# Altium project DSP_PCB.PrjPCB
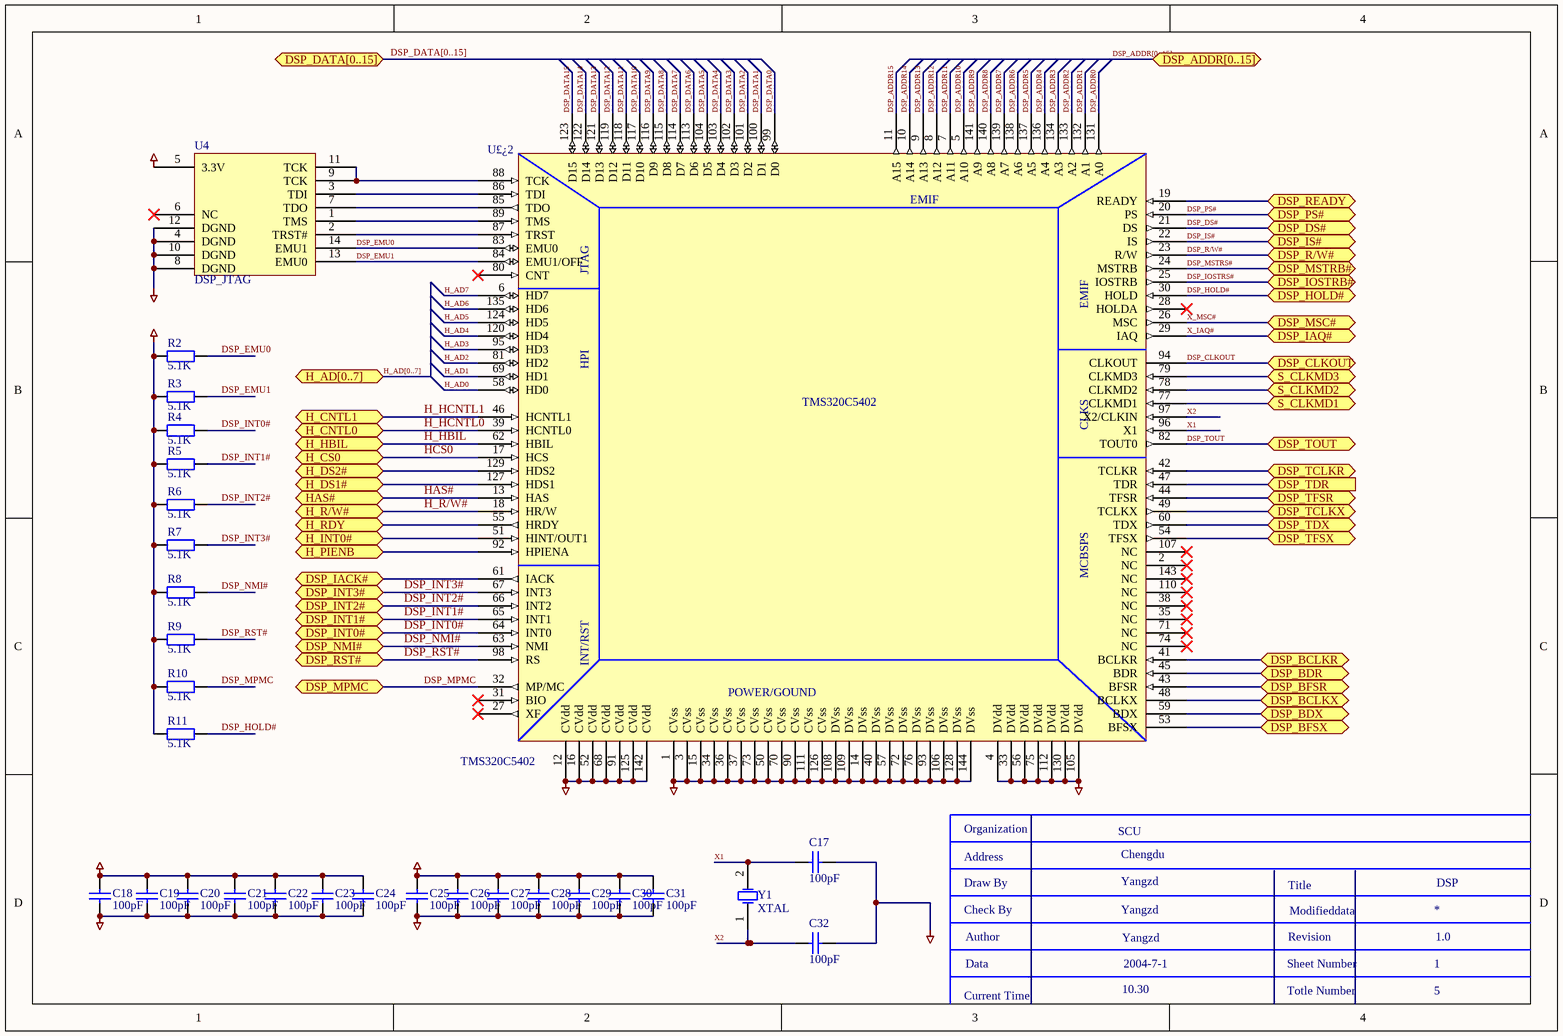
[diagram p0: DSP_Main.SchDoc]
7 sheets, 120 parts. Net scope: flat (ports and power ports of the same name join across sheets).
Sheets:
  DSP_Main.SchDoc
  CPLD.SchDoc
  Memory.SchDoc
  Interface.SchDoc
  Interface2.SchDoc
  Buffer.SchDoc
  Power.SchDoc

## Sheet DSP_Main.SchDoc: DSP
size A4; Date: 2004-7-1; CheckedBy: Yangzd; Author: Yangzd; DrawnBy: Yangzd; Organization: SCU; Address1: Chengdu; DocumentNumber: 1; Revision: 1.0; SheetNumber: 1; SheetTotal: 5

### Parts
C17  100pF  [CC2012-0805]
C18  100pF  [CC2012-0805]
C19  100pF  [CC2012-0805]
C20  100pF  [CC2012-0805]
C21  100pF  [CC2012-0805]
C22  100pF  [CC2012-0805]
C23  100pF  [CC2012-0805]
C24  100pF  [CC2012-0805]
C25  100pF  [CC2012-0805]
C26  100pF  [CC2012-0805]
C27  100pF  [CC2012-0805]
C28  100pF  [CC2012-0805]
C29  100pF  [CC2012-0805]
C30  100pF  [CC2012-0805]
C31  100pF  [CC2012-0805]
C32  100pF  [CC2012-0805]
R2  5.1K  [R2012-0805]
R3  5.1K  [R2012-0805]
R4  5.1K  [R2012-0805]
R5  5.1K  [R2012-0805]
R6  5.1K  [R2012-0805]
R7  5.1K  [R2012-0805]
R8  5.1K  [R2012-0805]
R9  5.1K  [R2012-0805]
R10  5.1K  [R2012-0805]
R11  5.1K  [R2012-0805]
U4  (no value)  [IDC14]
U£¿2  TMS320C5402  [QFP144]
Y1  XTAL  [BCY-W2/D3.1]

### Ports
DSP_ADDR[0..15], DSP_BCLKR, DSP_BCLKX, DSP_BDR, DSP_BDX, DSP_BFSR, DSP_BFSX, DSP_CLKOUT, DSP_DATA[0..15] (bidir), DSP_DS#, DSP_HOLD#, DSP_IACK#, DSP_IAQ#, DSP_INT0#, DSP_INT1#, DSP_INT2#, DSP_INT3#, DSP_IOSTRB#, DSP_IS#, DSP_MPMC, DSP_MSC#, DSP_MSTRB#, DSP_NMI#, DSP_PS#, DSP_R/W#, DSP_READY, DSP_RST#, DSP_TCLKR, DSP_TCLKX, DSP_TDR (in), DSP_TDX, DSP_TFSR, DSP_TFSX, DSP_TOUT, H_AD[0..7] (bidir), H_CNTL0, H_CNTL1, H_CS0, H_DS1#, H_DS2#, H_HBIL, H_INT0#, H_PIENB, H_R/W#, H_RDY, HAS#, S_CLKMD1, S_CLKMD2, S_CLKMD3

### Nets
1.8V: C25.2 C26.2 C27.2 C28.2 C29.2 C30.2 C31.2 U£¿2.12(CVdd) U£¿2.16(CVdd) U£¿2.52(CVdd) U£¿2.68(CVdd) U£¿2.91(CVdd) U£¿2.125(CVdd) U£¿2.142(CVdd)
3.3V: C18.2 C19.2 C20.2 C21.2 C22.2 C23.2 C24.2 R2.1 R3.1 R4.1 R5.1 R6.1 R7.1 R8.1 R9.1 R10.1 R11.1 U4.5(3.3V) U£¿2.4(DVdd) U£¿2.33(DVdd) U£¿2.56(DVdd) U£¿2.75(DVdd) U£¿2.105(DVdd) U£¿2.112(DVdd) U£¿2.130(DVdd)
DGND: C17.1 C18.1 C19.1 C20.1 C21.1 C22.1 C23.1 C24.1 C25.1 C26.1 C27.1 C28.1 C29.1 C30.1 C31.1 C32.1 U4.4(DGND) U4.8(DGND) U4.10(DGND) U4.12(DGND) U£¿2.1(CVss) U£¿2.3(CVss) U£¿2.14(DVss) U£¿2.15(CVss) U£¿2.34(CVss) U£¿2.36(CVss) U£¿2.37(CVss) U£¿2.40(DVss) U£¿2.50(CVss) U£¿2.57(DVss) U£¿2.70(CVss) U£¿2.72(DVss) U£¿2.73(CVss) U£¿2.76(DVss) U£¿2.90(CVss) U£¿2.93(DVss) U£¿2.106(DVss) U£¿2.108(DVss) U£¿2.109(DVss) U£¿2.111(CVss) U£¿2.126(CVss) U£¿2.128(DVss) U£¿2.144(DVss)
DSP_ADDR0: U£¿2.131(A0)
DSP_ADDR1: U£¿2.132(A1)
DSP_ADDR2: U£¿2.133(A2)
DSP_ADDR3: U£¿2.134(A3)
DSP_ADDR4: U£¿2.136(A4)
DSP_ADDR5: U£¿2.137(A5)
DSP_ADDR6: U£¿2.138(A6)
DSP_ADDR7: U£¿2.139(A7)
DSP_ADDR8: U£¿2.140(A8)
DSP_ADDR9: U£¿2.141(A9)
DSP_ADDR10: U£¿2.5(A10)
DSP_ADDR11: U£¿2.7(A11)
DSP_ADDR12: U£¿2.8(A12)
DSP_ADDR13: U£¿2.9(A13)
DSP_ADDR14: U£¿2.10(A14)
DSP_ADDR15: U£¿2.11(A15)
DSP_CLKOUT: U£¿2.94(CLKOUT) ; port DSP_CLKOUT
DSP_DATA0: U£¿2.99(D0)
DSP_DATA1: U£¿2.100(D1)
DSP_DATA2: U£¿2.101(D2)
DSP_DATA3: U£¿2.102(D3)
DSP_DATA4: U£¿2.103(D4)
DSP_DATA5: U£¿2.104(D5)
DSP_DATA6: U£¿2.113(D6)
DSP_DATA7: U£¿2.114(D7)
DSP_DATA8: U£¿2.115(D8)
DSP_DATA9: U£¿2.116(D9)
DSP_DATA10: U£¿2.117(D10)
DSP_DATA11: U£¿2.118(D11)
DSP_DATA12: U£¿2.119(D12)
DSP_DATA13: U£¿2.121(D13)
DSP_DATA14: U£¿2.122(D14)
DSP_DATA15: U£¿2.123(D15)
DSP_DS#: U£¿2.21(DS) ; port DSP_DS#
DSP_EMU0: R2.2 U4.14(EMU1) U£¿2.83(EMU0)
DSP_EMU1: R3.2 U4.13(EMU0) U£¿2.84(EMU1/OFF)
DSP_HOLD#: R11.2 U£¿2.30(HOLD) ; port DSP_HOLD#
DSP_INT0#: R4.2 U£¿2.64(INT0) ; port DSP_INT0#
DSP_INT1#: R5.2 U£¿2.65(INT1) ; port DSP_INT1#
DSP_INT2#: R6.2 U£¿2.66(INT2) ; port DSP_INT2#
DSP_INT3#: R7.2 U£¿2.67(INT3) ; port DSP_INT3#
DSP_IOSTRS#: U£¿2.25(IOSTRB) ; port DSP_IOSTRB#
DSP_IS#: U£¿2.22(IS) ; port DSP_IS#
DSP_MPMC: R10.2 U£¿2.32(MP/MC) ; port DSP_MPMC
DSP_MSTRS#: U£¿2.24(MSTRB) ; port DSP_MSTRB#
DSP_NMI#: R8.2 U£¿2.63(NMI) ; port DSP_NMI#
DSP_PS#: U£¿2.20(PS) ; port DSP_PS#
DSP_R/W#: U£¿2.23(R/W) ; port DSP_R/W#
DSP_RST#: R9.2 U£¿2.98(RS) ; port DSP_RST#
DSP_TOUT: U£¿2.82(TOUT0) ; port DSP_TOUT
H_AD0: U£¿2.58(HD0)
H_AD1: U£¿2.69(HD1)
H_AD2: U£¿2.81(HD2)
H_AD3: U£¿2.95(HD3)
H_AD4: U£¿2.120(HD4)
H_AD5: U£¿2.124(HD5)
H_AD6: U£¿2.135(HD6)
H_AD7: U£¿2.6(HD7)
H_HBIL: U£¿2.62(HBIL) ; port H_HBIL
H_HCNTL0: U£¿2.39(HCNTL0) ; port H_CNTL0
H_HCNTL1: U£¿2.46(HCNTL1) ; port H_CNTL1
H_R/W#: U£¿2.18(HR/W) ; port H_R/W#
HAS#: U£¿2.13(HAS) ; port HAS#
HCS0: U£¿2.17(HCS) ; port H_CS0
X1: C17.2 U£¿2.96(X1) Y1.2(OSC2)
X2: U£¿2.97(X2/CLKIN)
X_IAQ#: U£¿2.29(IAQ) ; port DSP_IAQ#
X_MSC#: U£¿2.26(MSC) ; port DSP_MSC#
NetC32_2: C32.2 Y1.1(OSC1)
NetJP3_8: U£¿2.127(HDS1) ; port H_DS1#
NetJP3_9: U£¿2.129(HDS2) ; port H_DS2#
NetR15_1: U£¿2.79(CLKMD3) ; port S_CLKMD3
NetR16_1: U£¿2.78(CLKMD2) ; port S_CLKMD2
NetR17_1: U£¿2.77(CLKMD1) ; port S_CLKMD1
NetU3_76: U£¿2.19(READY) ; port DSP_READY
NetU4_1: U4.1(TMS) U£¿2.89(TMS)
NetU4_2: U4.2(TRST#) U£¿2.87(TRST)
NetU4_3: U4.3(TDI) U£¿2.86(TDI)
NetU4_7: U4.7(TDO) U£¿2.85(TDO)
NetU4_9: U4.9(TCK) U4.11(TCK) U£¿2.88(TCK)
NetU5_16: U£¿2.47(TDR) ; port DSP_TDR
NetU5_17: U£¿2.45(BDR) ; port DSP_BDR
NetU5_19: U£¿2.44(TFSR) ; port DSP_TFSR
NetU5_20: U£¿2.43(BFSR) ; port DSP_BFSR
NetU5_22: U£¿2.42(TCLKR) ; port DSP_TCLKR
NetU5_23: U£¿2.41(BCLKR) ; port DSP_BCLKR
NetU5_35: U£¿2.48(BCLKX) ; port DSP_BCLKX
NetU5_36: U£¿2.49(TCLKX) ; port DSP_TCLKX
NetU5_37: U£¿2.51(HINT/OUT1) ; port H_INT0#
NetU5_38: U£¿2.53(BFSX) ; port DSP_BFSX
NetU5_40: U£¿2.54(TFSX) ; port DSP_TFSX
NetU5_41: U£¿2.55(HRDY) ; port H_RDY
NetU5_43: U£¿2.59(BDX) ; port DSP_BDX
NetU£¿2_60: U£¿2.60(TDX) ; port DSP_TDX
NetU£¿2_61: U£¿2.61(IACK) ; port DSP_IACK#
NetU£¿2_92: U£¿2.92(HPIENA) ; port H_PIENB

Not connected (* = marked no-connect by the designer): U4 6(NC)*; U£¿2 2(NC)* 27(XF)* 28(HOLDA)* 31(BIO)* 35(NC)* 38(NC)* 71(NC)* 74(NC)* 80(CNT)* 107(NC)* 110(NC)* 143(NC)*

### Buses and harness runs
bus DSP_ADDR[0..15] = port DSP_ADDR[0..15]
bus DSP_DATA[0..15] = port DSP_DATA[0..15]
bus H_AD[0..7] = port H_AD[0..7]

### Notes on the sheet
- Organization
- Draw By
- Check By
- Address
- Title
- Modifieddata
- Data
- Author
- Sheet Number
- Revision
- Current Time
- Totle Number
- Labels drawn without touching a wire or pin: X2

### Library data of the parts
C17-C32 = Cap: Capacitor; Manufacturer: Generic Components; Class I: Passive
R2-R11 = Res2: Resistor; Manufacturer: Generic Components; Class I: Passive
U4 = DSP_JTAG
U£¿2 = TMS320C5402: FIXED-POINT DIGITAL SIGNAL PROCESSORS
Y1 = XTAL: Crystal Oscillator; Manufacturer: Generic Components

## Sheet CPLD.SchDoc
size A4
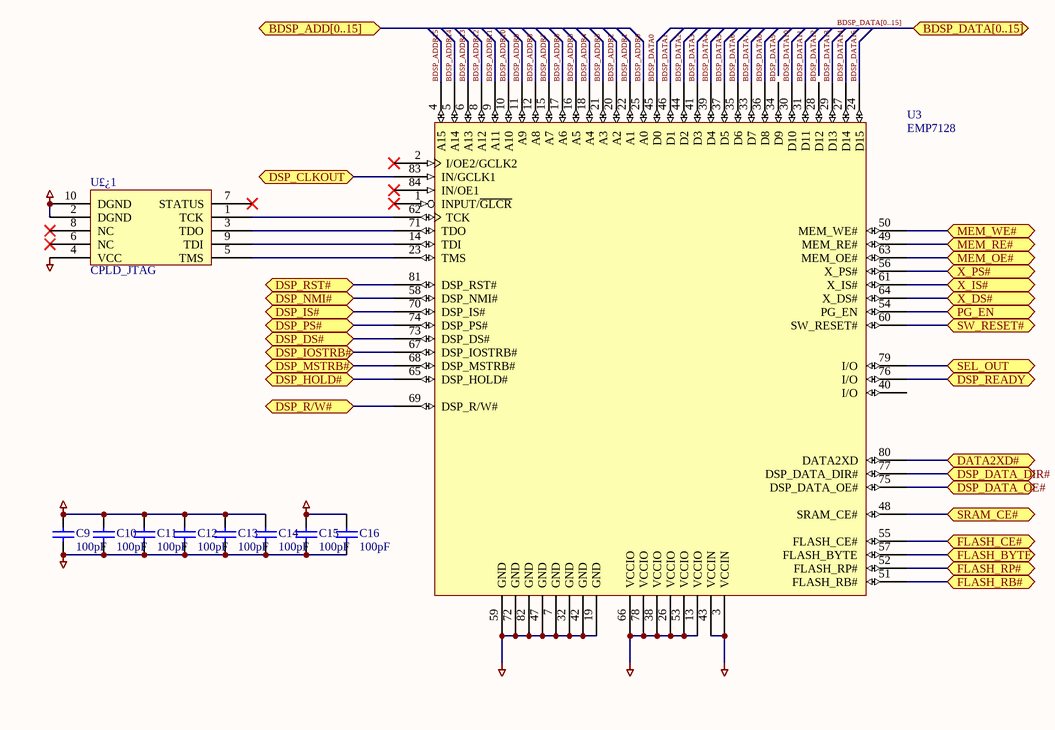
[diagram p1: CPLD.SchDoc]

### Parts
(Parts that share a designator on the sheet are numbered #1, #2 ... from top to bottom, then left to right.)
C9#1  100pF  [CC2012-0805]
C10#1  100pF  [CC2012-0805]
C11#1  100pF  [CC2012-0805]
C12#1  100pF  [CC2012-0805]
C13  100pF  [CC2012-0805]
C14  100pF  [CC2012-0805]
C15  100pF  [CC2012-0805]
C16  100pF  [CC2012-0805]
U3  EMP7128  [HPLCC84]
U£¿1  CPLD_JTAG  [IDC10]

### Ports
BDSP_ADD[0..15], BDSP_DATA[0..15], DATA2XD#, DSP_CLKOUT, DSP_DATA_DIR#, DSP_DATA_OE#, DSP_DS#, DSP_HOLD#, DSP_IOSTRB#, DSP_IS#, DSP_MSTRB#, DSP_NMI#, DSP_PS#, DSP_R/W#, DSP_READY, DSP_RST#, FLASH_BYTE, FLASH_CE#, FLASH_RB#, FLASH_RP#, MEM_OE#, MEM_RE#, MEM_WE#, PG_EN, SEL_OUT, SRAM_CE#, SW_RESET#, X_DS#, X_IS#, X_PS#

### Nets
3.3V: C9#1.1 C10#1.2 C11#1.2 C12#1.2 C13.2 C14.2 U3.13(VCCIO) U3.26(VCCIO) U3.38(VCCIO) U3.53(VCCIO) U3.66(VCCIO) U3.78(VCCIO) U£¿1.4(VCC)
5V: C15.2 C16.2 U3.3(VCCIN) U3.43(VCCIN)
DGND: C9#1.2 C10#1.1 C11#1.1 C12#1.1 C13.1 C14.1 C15.1 C16.1 U3.7(GND) U3.19(GND) U3.32(GND) U3.42(GND) U3.47(GND) U3.59(GND) U3.72(GND) U3.82(GND) U£¿1.2(DGND) U£¿1.10(DGND)
BDSP_ADDR0: U3.25(A0)
BDSP_ADDR1: U3.22(A1)
BDSP_ADDR2: U3.20(A2)
BDSP_ADDR3: U3.21(A3)
BDSP_ADDR4: U3.18(A4)
BDSP_ADDR5: U3.16(A5)
BDSP_ADDR6: U3.17(A6)
BDSP_ADDR7: U3.15(A7)
BDSP_ADDR8: U3.12(A8)
BDSP_ADDR9: U3.11(A9)
BDSP_ADDR10: U3.10(A10)
BDSP_ADDR11: U3.9(A11)
BDSP_ADDR12: U3.8(A12)
BDSP_ADDR13: U3.6(A13)
BDSP_ADDR14: U3.5(A14)
BDSP_ADDR15: U3.4(A15)
BDSP_DATA0: U3.45(D0)
BDSP_DATA1: U3.46(D1)
BDSP_DATA2: U3.44(D2)
BDSP_DATA3: U3.41(D3)
BDSP_DATA4: U3.39(D4)
BDSP_DATA5: U3.37(D5)
BDSP_DATA6: U3.35(D6)
BDSP_DATA7: U3.33(D7)
BDSP_DATA8: U3.36(D8)
BDSP_DATA9: U3.34(D9)
BDSP_DATA10: U3.30(D10)
BDSP_DATA11: U3.31(D11)
BDSP_DATA12: U3.28(D12)
BDSP_DATA13: U3.29(D13)
BDSP_DATA14: U3.27(D14)
BDSP_DATA15: U3.24(D15)
DSP_CLKOUT: U3.83(IN/GCLK1) ; port DSP_CLKOUT
DSP_DATA_DIR: U3.77(DSP_DATA_DIR#) ; port DSP_DATA_DIR#
DSP_DATA_OE#: U3.75(DSP_DATA_OE#) ; port DSP_DATA_OE#
DSP_DS#: U3.73(DSP_DS#) ; port DSP_DS#
DSP_HOLD#: U3.65(DSP_HOLD#) ; port DSP_HOLD#
DSP_IOSTRS#: U3.67(DSP_IOSTRB#) ; port DSP_IOSTRB#
DSP_IS#: U3.70(DSP_IS#) ; port DSP_IS#
DSP_MSTRS#: U3.68(DSP_MSTRB#) ; port DSP_MSTRB#
DSP_NMI#: U3.58(DSP_NMI#) ; port DSP_NMI#
DSP_PS#: U3.74(DSP_PS#) ; port DSP_PS#
DSP_R/W#: U3.69(DSP_R/W#) ; port DSP_R/W#
DSP_RST#: U3.81(DSP_RST#) ; port DSP_RST#
FLASH_BYTE: U3.57(FLASH_BYTE) ; port FLASH_BYTE
FLASH_CE#: U3.55(FLASH_CE#) ; port FLASH_CE#
FLASH_RB: U3.51(FLASH_RB#) ; port FLASH_RB#
FLASH_RP: U3.52(FLASH_RP#) ; port FLASH_RP#
MEM_R#: U3.49(MEM_RE#) ; port MEM_RE#
MEM_WE#: U3.50(MEM_WE#) ; port MEM_WE#
SRAM_CE#: U3.48(SRAM_CE#) ; port SRAM_CE#
NetR14_1: U3.60(SW_RESET#) ; port SW_RESET#
NetU3_14: U3.14(TDI) U£¿1.9(TDI)
NetU3_23: U3.23(TMS) U£¿1.5(TMS)
NetU3_54: U3.54(PG_EN) ; port PG_EN
NetU3_56: U3.56(X_PS#) ; port X_PS#
NetU3_61: U3.61(X_IS#) ; port X_IS#
NetU3_62: U3.62(TCK) U£¿1.1(TCK)
NetU3_63: U3.63(MEM_OE#) ; port MEM_OE#
NetU3_64: U3.64(X_DS#) ; port X_DS#
NetU3_71: U3.71(TDO) U£¿1.3(TDO)
NetU3_76: U3.76(I/O) ; port DSP_READY
NetU3_79: U3.79(I/O) ; port SEL_OUT
NetU3_80: U3.80(DATA2XD) ; port DATA2XD#

Not connected (* = marked no-connect by the designer): U3 1(INPUT/~{GLCR})* 2(I/OE2/GCLK2)* 40(I/O) 84(IN/OE1)*; U£¿1 6(NC)* 7(STATUS)* 8(NC)*

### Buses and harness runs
bus BDSP_DATA[0..15] = port BDSP_DATA[0..15]

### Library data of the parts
C9#1 C10#1 C11#1 C12#1 C13-C16 = Cap: as C17 on sheet DSP_Main
U3 = EMP7128: CPLD

## Sheet Memory.SchDoc
size A4
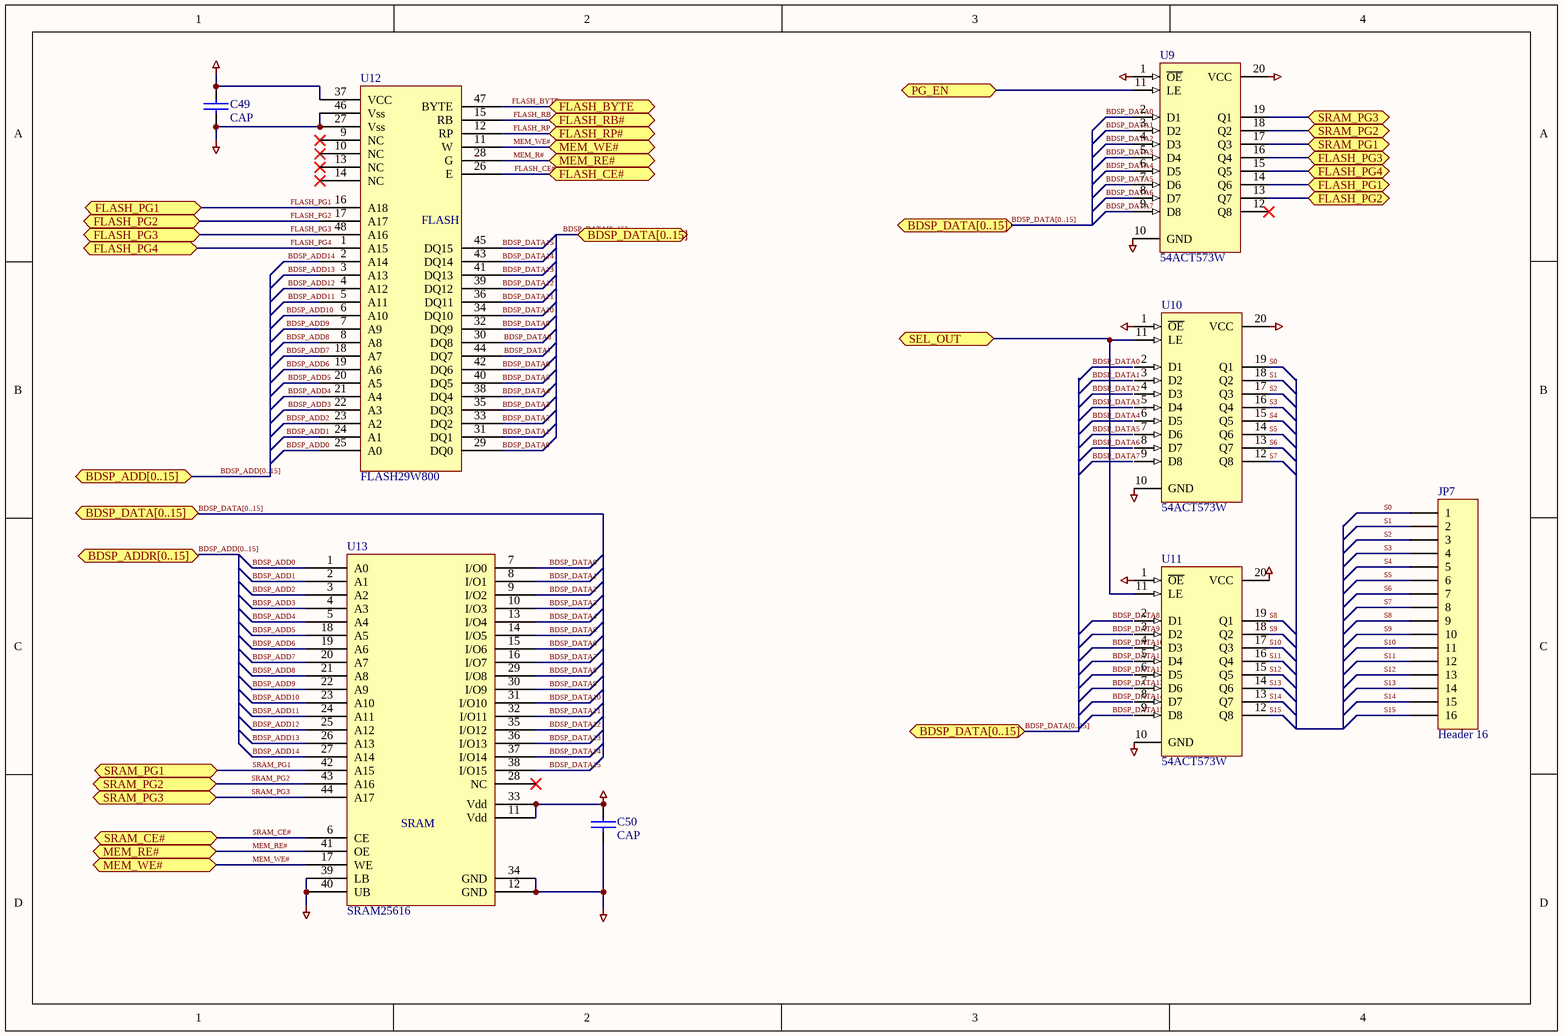
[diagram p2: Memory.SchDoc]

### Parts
C49  CAP  [CC2012-0805]
C50  CAP  [CC2012-0805]
JP7  Header 16  [HDR1X16]
U9  54ACT573W  [CDFP-G20/C10]
U10  54ACT573W  [CDFP-G20/C10]
U11  54ACT573W  [CDFP-G20/C10]
U12  FLASH29W800  [TSSO12X20-G48/P.5]
U13  SRAM25616  [TSOP44]

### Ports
BDSP_ADD[0..15], BDSP_ADDR[0..15], BDSP_DATA[0..15], FLASH_BYTE, FLASH_CE#, FLASH_PG1, FLASH_PG2, FLASH_PG3, FLASH_PG4, FLASH_RB#, FLASH_RP#, MEM_RE#, MEM_WE#, PG_EN, SEL_OUT, SRAM_CE#, SRAM_PG1, SRAM_PG2, SRAM_PG3

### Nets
3.3V: C49.1 C50.1 U12.37(VCC) U13.11(Vdd) U13.33(Vdd)
5V: U9.20(VCC) U10.20(VCC) U11.20(VCC)
DGND: C49.2 C50.2 U9.1(~{OE}) U9.10(GND) U10.1(~{OE}) U10.10(GND) U11.1(~{OE}) U11.10(GND) U12.27(Vss) U12.46(Vss) U13.12(GND) U13.34(GND) U13.39(LB) U13.40(UB)
BDSP_ADD0: U12.25(A0) U13.1(A0)
BDSP_ADD1: U12.24(A1) U13.2(A1)
BDSP_ADD2: U12.23(A2) U13.3(A2)
BDSP_ADD3: U12.22(A3) U13.4(A3)
BDSP_ADD4: U12.21(A4) U13.5(A4)
BDSP_ADD5: U12.20(A5) U13.18(A5)
BDSP_ADD6: U12.19(A6) U13.19(A6)
BDSP_ADD7: U12.18(A7) U13.20(A7)
BDSP_ADD8: U12.8(A8) U13.21(A8)
BDSP_ADD9: U12.7(A9) U13.22(A9)
BDSP_ADD10: U12.6(A10) U13.23(A10)
BDSP_ADD11: U12.5(A11) U13.24(A11)
BDSP_ADD12: U12.4(A12) U13.25(A12)
BDSP_ADD13: U12.3(A13) U13.26(A13)
BDSP_ADD14: U12.2(A14) U13.27(A14)
BDSP_DATA0: U9.2(D1) U12.29(DQ0) U13.7(I/O0)
BDSP_DATA1: U9.3(D2) U12.31(DQ1) U13.8(I/O1)
BDSP_DATA2: U9.4(D3) U12.33(DQ2) U13.9(I/O2)
BDSP_DATA3: U9.5(D4) U12.35(DQ3) U13.10(I/O3)
BDSP_DATA4: U9.6(D5) U12.38(DQ4) U13.13(I/O4)
BDSP_DATA5: U9.7(D6) U12.40(DQ5) U13.14(I/O5)
BDSP_DATA6: U9.8(D7) U12.42(DQ6) U13.15(I/O6)
BDSP_DATA7: U9.9(D8) U12.44(DQ7) U13.16(I/O7)
BDSP_DATA8: U12.30(DQ8) U13.29(I/O8)
BDSP_DATA9: U12.32(DQ9) U13.30(I/O9)
BDSP_DATA10: U12.34(DQ10) U13.31(I/O10)
BDSP_DATA11: U12.36(DQ11) U13.32(I/O11)
BDSP_DATA12: U12.39(DQ12) U13.35(I/O12)
BDSP_DATA13: U12.41(DQ13) U13.36(I/O13)
BDSP_DATA14: U12.43(DQ14) U13.37(I/O14)
BDSP_DATA15: U12.45(DQ15) U13.38(I/O15)
FLASH_BYTE: U12.47(BYTE) ; port FLASH_BYTE
FLASH_CE#: U12.26(E) ; port FLASH_CE#
FLASH_PG1: U9.14(Q6) U12.16(A18) ; port FLASH_PG1
FLASH_PG2: U9.13(Q7) U12.17(A17) ; port FLASH_PG2
FLASH_PG3: U9.16(Q4) U12.48(A16) ; port FLASH_PG3
FLASH_PG4: U9.15(Q5) U12.1(A15) ; port FLASH_PG4
FLASH_RB: U12.15(RB) ; port FLASH_RB#
FLASH_RP: U12.12(RP) ; port FLASH_RP#
MEM_R#: U12.28(G) U13.41(OE) ; port MEM_RE#  [also labelled MEM_RE#]
MEM_WE#: U12.11(W) U13.17(WE) ; port MEM_WE#
S0: JP7.1 U10.19(Q1)
S1: JP7.2 U10.18(Q2)
S2: JP7.3 U10.17(Q3)
S3: JP7.4 U10.16(Q4)
S4: JP7.5 U10.15(Q5)
S5: JP7.6 U10.14(Q6)
S6: JP7.7 U10.13(Q7)
S7: JP7.8 U10.12(Q8)
S8: JP7.9 U11.19(Q1)
S9: JP7.10 U11.18(Q2)
S10: JP7.11 U11.17(Q3)
S11: JP7.12 U11.16(Q4)
S12: JP7.13 U11.15(Q5)
S13: JP7.14 U11.14(Q6)
S14: JP7.15 U11.13(Q7)
S15: JP7.16 U11.12(Q8)
SRAM_CE#: U13.6(CE) ; port SRAM_CE#
SRAM_PG1: U9.17(Q3) U13.42(A15) ; port SRAM_PG1
SRAM_PG2: U9.18(Q2) U13.43(A16) ; port SRAM_PG2
SRAM_PG3: U9.19(Q1) U13.44(A17) ; port SRAM_PG3
NetU3_54: U9.11(LE) ; port PG_EN
NetU3_79: U10.11(LE) U11.11(LE) ; port SEL_OUT

Not connected (* = marked no-connect by the designer): U9 12(Q8); U10 2(D1) 3(D2) 4(D3) 5(D4) 6(D5) 7(D6) 8(D7) 9(D8); U11 2(D1) 3(D2) 4(D3) 5(D4) 6(D5) 7(D6) 8(D7) 9(D8); U12 9(NC)* 10(NC)* 13(NC)* 14(NC)*; U13 28(NC)*

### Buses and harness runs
bus BDSP_ADD[0..15]
bus BDSP_ADD[0..15] = port BDSP_ADD[0..15]
bus BDSP_DATA[0..15]
bus BDSP_DATA[0..15] = port BDSP_DATA[0..15]

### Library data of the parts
C49 C50 = CAP: Capacitor
JP7 = Header 16: Header, 16-Pin; Manufacturer: Generic Components; Class I: Connector
U9-U11 = 54ACT573W: Octal D-Type Transparent Latch with 3-State Outputs; Manufacturer: Texas Instruments; Package Information: Latest Revision: Jan-1995; Class I: Logic
U12 = FLASH29W800: FLASH RAM
U13 = SRAM25616: SRAM

## Sheet Interface.SchDoc
size A4
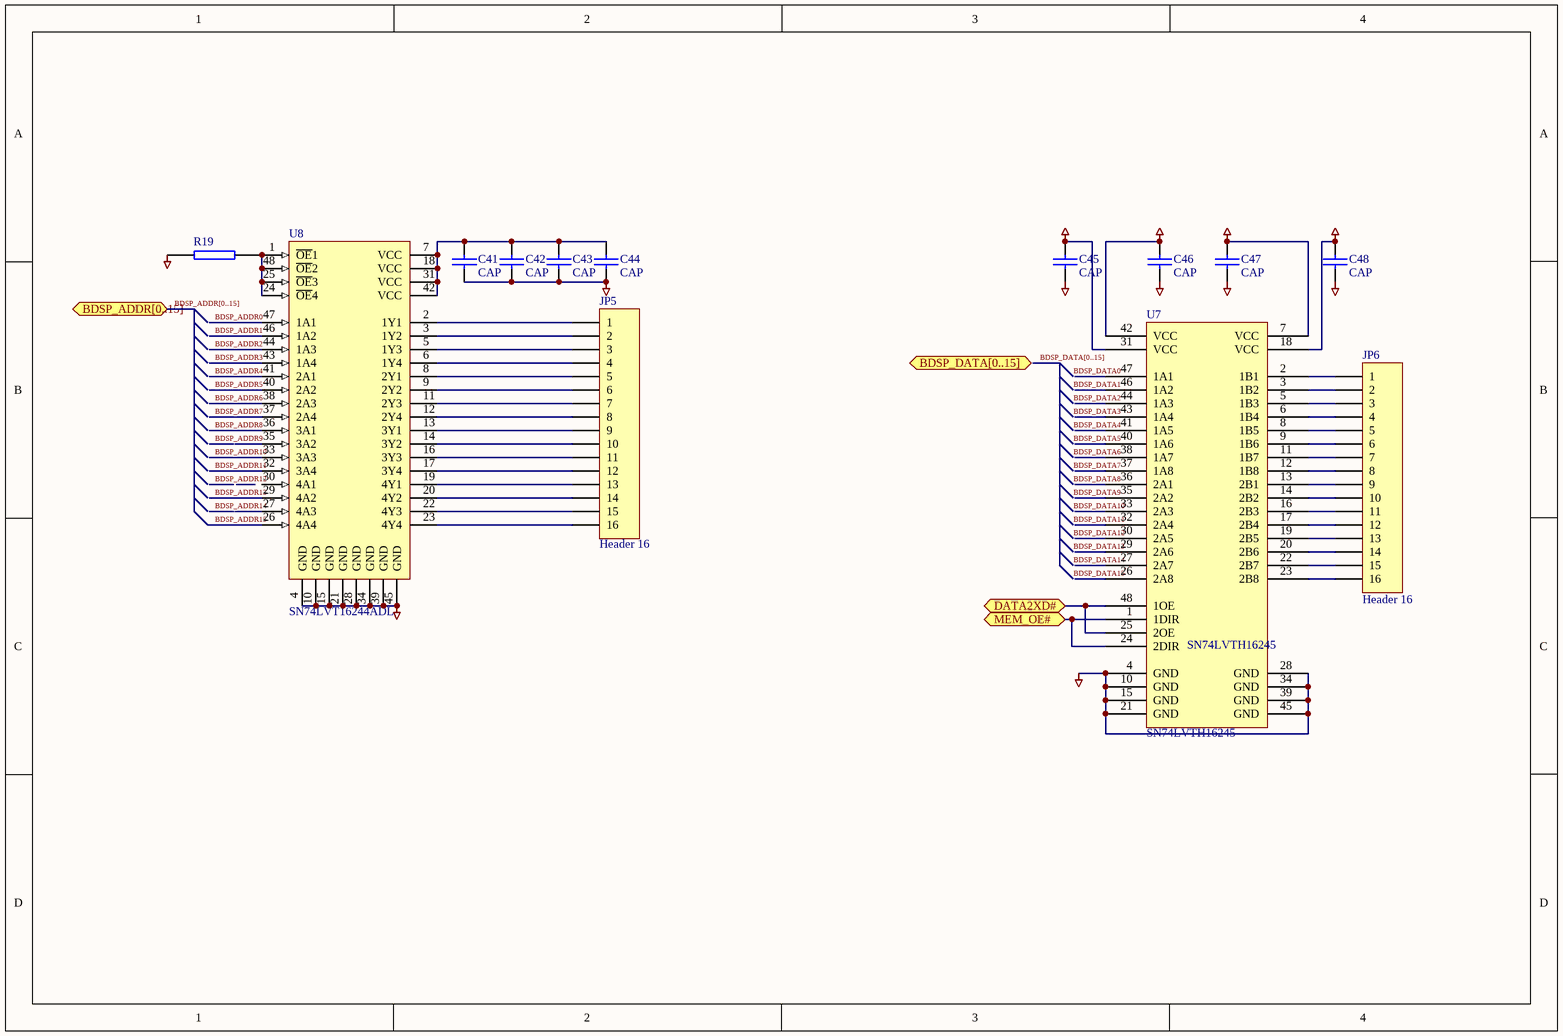
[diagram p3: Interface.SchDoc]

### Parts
C41  CAP  [CC2012-0805]
C42  CAP  [CC2012-0805]
C43  CAP  [CC2012-0805]
C44  CAP  [CC2012-0805]
C45  CAP  [CC2012-0805]
C46  CAP  [CC2012-0805]
C47  CAP  [CC2012-0805]
C48  CAP  [CC2012-0805]
JP5  Header 16  [HDR1X16]
JP6  Header 16  [HDR1X16]
R19  (no value)  [R2012-0805]
U7  SN74LVTH16245  [TSOP48]
U8  SN74LVT16244ADL  [SSO-G48]

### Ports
BDSP_ADDR[0..15], BDSP_DATA[0..15], DATA2XD#, MEM_OE#

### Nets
3.3V: C45.1 C46.1 C47.1 C48.1 U7.7(VCC) U7.18(VCC) U7.31(VCC) U7.42(VCC)
DGND: C41.2 C42.2 C43.2 C44.2 C45.2 C46.2 C47.2 C48.2 R19.2 U7.4(GND) U7.10(GND) U7.15(GND) U7.21(GND) U7.28(GND) U7.34(GND) U7.39(GND) U7.45(GND) U8.4(GND) U8.10(GND) U8.15(GND) U8.21(GND) U8.28(GND) U8.34(GND) U8.39(GND) U8.45(GND)
BDSP_ADDR0: U8.47(1A1)
BDSP_ADDR1: U8.46(1A2)
BDSP_ADDR2: U8.44(1A3)
BDSP_ADDR3: U8.43(1A4)
BDSP_ADDR4: U8.41(2A1)
BDSP_ADDR5: U8.40(2A2)
BDSP_ADDR6: U8.38(2A3)
BDSP_ADDR7: U8.37(2A4)
BDSP_ADDR8: U8.36(3A1)
BDSP_ADDR10: U8.33(3A3)
BDSP_ADDR11: U8.32(3A4)
BDSP_ADDR13: U8.29(4A2)
BDSP_ADDR15: U8.26(4A4)
NetC41_1: C41.1 C42.1 C43.1 C44.1 U8.7(VCC) U8.18(VCC) U8.31(VCC) U8.42(VCC)
NetJP5_1: JP5.1 U8.2(1Y1)
NetJP5_2: JP5.2 U8.3(1Y2)
NetJP5_3: JP5.3 U8.5(1Y3)
NetJP5_4: JP5.4 U8.6(1Y4)
NetJP5_5: JP5.5 U8.8(2Y1)
NetJP5_6: JP5.6 U8.9(2Y2)
NetJP5_7: JP5.7 U8.11(2Y3)
NetJP5_8: JP5.8 U8.12(2Y4)
NetJP5_9: JP5.9 U8.13(3Y1)
NetJP5_10: JP5.10 U8.14(3Y2)
NetJP5_11: JP5.11 U8.16(3Y3)
NetJP5_12: JP5.12 U8.17(3Y4)
NetJP5_13: JP5.13 U8.19(4Y1)
NetJP5_14: JP5.14 U8.20(4Y2)
NetJP5_15: JP5.15 U8.22(4Y3)
NetJP5_16: JP5.16 U8.23(4Y4)
NetJP6_1: JP6.1 U7.2(1B1)
NetJP6_2: JP6.2 U7.3(1B2)
NetJP6_3: JP6.3 U7.5(1B3)
NetJP6_4: JP6.4 U7.6(1B4)
NetJP6_5: JP6.5 U7.8(1B5)
NetJP6_6: JP6.6 U7.9(1B6)
NetJP6_7: JP6.7 U7.11(1B7)
NetJP6_8: JP6.8 U7.12(1B8)
NetJP6_9: JP6.9 U7.13(2B1)
NetJP6_10: JP6.10 U7.14(2B2)
NetJP6_11: JP6.11 U7.16(2B3)
NetJP6_12: JP6.12 U7.17(2B4)
NetJP6_13: JP6.13 U7.19(2B5)
NetJP6_14: JP6.14 U7.20(2B6)
NetJP6_15: JP6.15 U7.22(2B7)
NetJP6_16: JP6.16 U7.23(2B8)
NetR19_1: R19.1 U8.1(~{OE}1) U8.24(~{OE}4) U8.25(~{OE}3) U8.48(~{OE}2)
NetU3_63: U7.1(1DIR) U7.24(2DIR) ; port MEM_OE#
NetU3_80: U7.25(2OE) U7.48(1OE) ; port DATA2XD#

Not connected (* = marked no-connect by the designer): U7 26(2A8) 27(2A7) 29(2A6) 30(2A5) 32(2A4) 33(2A3) 35(2A2) 36(2A1) 37(1A8) 38(1A7) 40(1A6) 41(1A5) 43(1A4) 44(1A3) 46(1A2) 47(1A1); U8 27(4A3) 30(4A1) 35(3A2)

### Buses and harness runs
bus BDSP_ADDR[0..15] = port BDSP_ADDR[0..15]
bus BDSP_DATA[0..15]

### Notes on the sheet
- Labels drawn without touching a wire or pin: BDSP_DATA0, BDSP_DATA1, BDSP_DATA2, BDSP_DATA3, BDSP_DATA4, BDSP_DATA5, BDSP_DATA6, BDSP_DATA7, BDSP_DATA8, BDSP_DATA9, BDSP_DATA10, BDSP_DATA11, BDSP_DATA12, BDSP_DATA13, BDSP_DATA14, BDSP_DATA15

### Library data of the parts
C41-C48 = CAP: Capacitor
JP5 JP6 = Header 16: as JP7 on sheet Memory
R19 = RES2
U8 = SN74LVT16244ADL: 3.3-V ABT 16-Bit Buffer/Driver with 3-State Outputs; Manufacturer: Texas Instruments; Package Information: Latest Revision: Jan-1998; Class I: Logic; Class II: Buffer/Line Driver

## Sheet Interface2.SchDoc
size A4
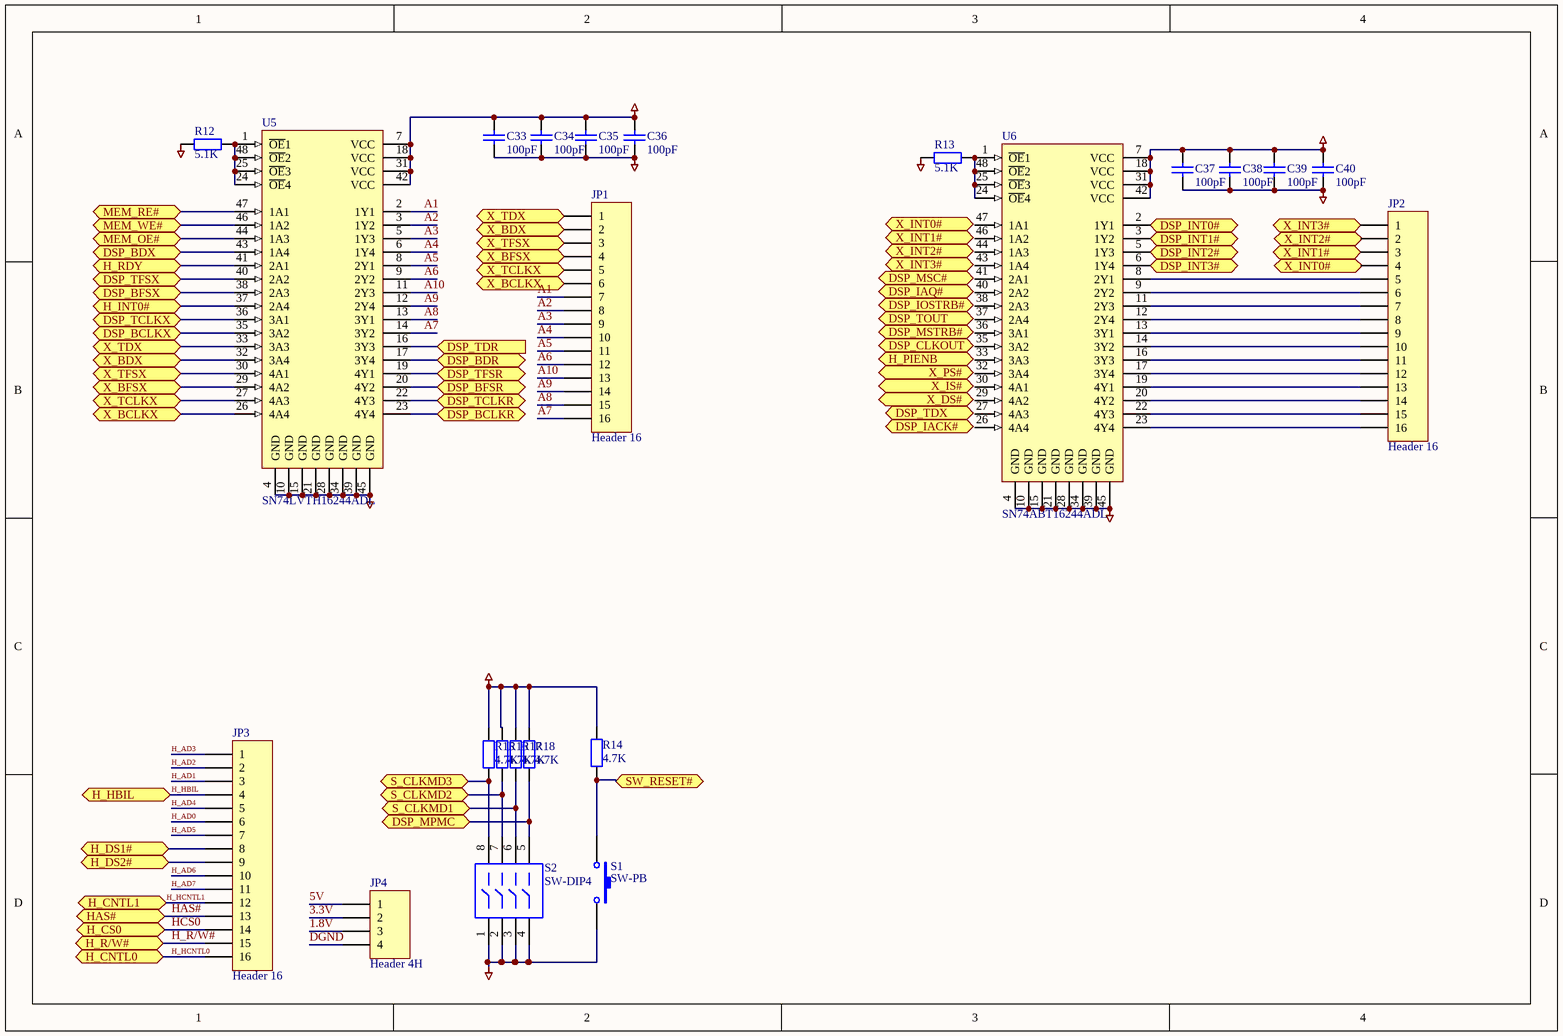
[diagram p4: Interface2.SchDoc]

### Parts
C33  100pF  [CC2012-0805]
C34  100pF  [CC2012-0805]
C35  100pF  [CC2012-0805]
C36  100pF  [CC2012-0805]
C37  100pF  [CC2012-0805]
C38  100pF  [CC2012-0805]
C39  100pF  [CC2012-0805]
C40  100pF  [CC2012-0805]
JP1  Header 16  [HDR1X16]
JP2  Header 16  [HDR1X16]
JP3  Header 16  [HDR1X16]
JP4  Header 4H  [HDR1X4H]
R12  5.1K  [R2012-0805]
R13  5.1K  [R2012-0805]
R14  4.7K  [R2012-0805]
R15  4.7K  [R2012-0805]
R16  4.7K  [R2012-0805]
R17  4.7K  [R2012-0805]
R18  4.7K  [R2012-0805]
S1  SW-PB  [SPST-2]
S2  SW-DIP4  [DIP-8]
U5  SN74LVTH16244ADL  [SSO-G48]
U6  SN74ABT16244ADL  [SSO-G48]

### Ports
DSP_BCLKR, DSP_BCLKX, DSP_BDR, DSP_BDX, DSP_BFSR, DSP_BFSX, DSP_CLKOUT, DSP_IACK#, DSP_IAQ#, DSP_INT0#, DSP_INT1#, DSP_INT2#, DSP_INT3#, DSP_IOSTRB#, DSP_MPMC, DSP_MSC#, DSP_MSTRB#, DSP_TCLKR, DSP_TCLKX, DSP_TDR (in), DSP_TDX, DSP_TFSR, DSP_TFSX, DSP_TOUT, H_CNTL0, H_CNTL1, H_CS0, H_DS1#, H_DS2#, H_HBIL, H_INT0#, H_PIENB, H_R/W#, H_RDY, HAS#, MEM_OE#, MEM_RE#, MEM_WE#, S_CLKMD1, S_CLKMD2, S_CLKMD3, SW_RESET#, X_BCLKX, X_BDX, X_BFSX, X_DS#, X_INT0#, X_INT1#, X_INT2#, X_INT3#, X_IS#, X_PS#, X_TCLKX, X_TDX, X_TFSX

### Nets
3.3V: C33.2 C34.2 C35.2 C36.2 C37.2 C38.2 C39.2 C40.2 JP4.2 R14.2 R15.2 R16.2 R17.2 R18.2 U5.7(VCC) U5.18(VCC) U5.31(VCC) U5.42(VCC) U6.7(VCC) U6.18(VCC) U6.31(VCC) U6.42(VCC)
DGND: C33.1 C34.1 C35.1 C36.1 C37.1 C38.1 C39.1 C40.1 JP4.4 R12.1 R13.1 S2.1 U5.4(GND) U5.10(GND) U5.15(GND) U5.21(GND) U5.28(GND) U5.34(GND) U5.39(GND) U5.45(GND) U6.4(GND) U6.10(GND) U6.15(GND) U6.21(GND) U6.28(GND) U6.34(GND) U6.39(GND) U6.45(GND)
1.8V: JP4.3
5V: JP4.1
A1: JP1.7 U5.2(1Y1)
A2: JP1.8 U5.3(1Y2)
A3: JP1.9 U5.5(1Y3)
A4: JP1.10 U5.6(1Y4)
A5: JP1.11 U5.8(2Y1)
A6: JP1.12 U5.9(2Y2)
A7: JP1.16 U5.14(3Y2)
A8: JP1.15 U5.13(3Y1)
A9: JP1.14 U5.12(2Y4)
A10: JP1.13 U5.11(2Y3)
DSP_INT0#: U6.2(1Y1) ; port DSP_INT0#
DSP_INT1#: U6.3(1Y2) ; port DSP_INT1#
DSP_INT2#: U6.5(1Y3) ; port DSP_INT2#
DSP_INT3#: U6.6(1Y4) ; port DSP_INT3#
DSP_MPMC: R18.1 S2.5 ; port DSP_MPMC
H_AD0: JP3.6
H_AD1: JP3.3
H_AD2: JP3.2
H_AD3: JP3.1
H_AD4: JP3.5
H_AD5: JP3.7
H_AD6: JP3.10
H_AD7: JP3.11
H_HBIL: JP3.4 ; port H_HBIL
H_HCNTL0: JP3.16 ; port H_CNTL0
H_HCNTL1: JP3.12 ; port H_CNTL1
H_R/W#: JP3.15 ; port H_R/W#
HAS#: JP3.13 ; port HAS#
HCS0: JP3.14 ; port H_CS0
MEM_R#: U5.47(1A1) ; port MEM_RE#
MEM_WE#: U5.46(1A2) ; port MEM_WE#
NetJP1_1: JP1.1 U5.33(3A3) ; port X_TDX
NetJP1_2: JP1.2 U5.32(3A4) ; port X_BDX
NetJP1_3: JP1.3 U5.30(4A1) ; port X_TFSX
NetJP1_4: JP1.4 U5.29(4A2) ; port X_BFSX
NetJP1_5: JP1.5 U5.27(4A3) ; port X_TCLKX
NetJP1_6: JP1.6 U5.26(4A4) ; port X_BCLKX
NetJP2_1: JP2.1 ; port X_INT3#
NetJP2_3: JP2.3 ; port X_INT1#
NetJP2_5: JP2.5 U6.8(2Y1)
NetJP2_6: JP2.6 U6.9(2Y2)
NetJP2_7: JP2.7 U6.11(2Y3)
NetJP2_8: JP2.8 U6.12(2Y4)
NetJP2_9: JP2.9 U6.13(3Y1)
NetJP2_10: JP2.10 U6.14(3Y2)
NetJP2_11: JP2.11 U6.16(3Y3)
NetJP2_12: JP2.12 U6.17(3Y4)
NetJP2_13: JP2.13 U6.19(4Y1)
NetJP2_14: JP2.14 U6.20(4Y2)
NetJP2_15: JP2.15 U6.22(4Y3)
NetJP2_16: JP2.16 U6.23(4Y4)
NetJP3_8: JP3.8 ; port H_DS1#
NetJP3_9: JP3.9 ; port H_DS2#
NetR12_2: R12.2 U5.1(~{OE}1) U5.24(~{OE}4) U5.25(~{OE}3) U5.48(~{OE}2)
NetR13_2: R13.2 U6.1(~{OE}1) U6.24(~{OE}4) U6.25(~{OE}3) U6.48(~{OE}2)
NetR14_1: R14.1 S1.1 ; port SW_RESET#
NetR15_1: R15.1 S2.8 ; port S_CLKMD3
NetR16_1: R16.1 S2.7 ; port S_CLKMD2
NetR17_1: R17.1 S2.6 ; port S_CLKMD1
NetS1_2: S1.2 S2.2 S2.3 S2.4
NetU3_63: U5.44(1A3) ; port MEM_OE#
NetU5_16: U5.16(3Y3) ; port DSP_TDR
NetU5_17: U5.17(3Y4) ; port DSP_BDR
NetU5_19: U5.19(4Y1) ; port DSP_TFSR
NetU5_20: U5.20(4Y2) ; port DSP_BFSR
NetU5_22: U5.22(4Y3) ; port DSP_TCLKR
NetU5_23: U5.23(4Y4) ; port DSP_BCLKR
NetU5_35: U5.35(3A2) ; port DSP_BCLKX
NetU5_36: U5.36(3A1) ; port DSP_TCLKX
NetU5_37: U5.37(2A4) ; port H_INT0#
NetU5_38: U5.38(2A3) ; port DSP_BFSX
NetU5_40: U5.40(2A2) ; port DSP_TFSX
NetU5_41: U5.41(2A1) ; port H_RDY
NetU5_43: U5.43(1A4) ; port DSP_BDX

Not connected (* = marked no-connect by the designer): JP2 2 4; U6 26(4A4) 27(4A3) 29(4A2) 30(4A1) 32(3A4) 33(3A3) 35(3A2) 36(3A1) 37(2A4) 38(2A3) 40(2A2) 41(2A1) 43(1A4) 44(1A3) 46(1A2) 47(1A1)

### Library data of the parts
C33-C40 = Cap: as C17 on sheet DSP_Main
JP1-JP3 = Header 16: as JP7 on sheet Memory
JP4 = Header 4H: Header, 4-Pin,  Right Angle; Manufacturer: Generic Components; Class I: Connector
R12-R18 = Res2: as R2 on sheet DSP_Main
S1 = SW-PB: Switch; Manufacturer: Generic Components
S2 = SW-DIP4: DIP Switch; Manufacturer: Generic Components
U5 = SN74LVTH16244ADL: 3.3-V ABT 16-Bit Buffer/Driver with 3-State Outputs; Manufacturer: Texas Instruments; Package Information: Latest Revision: Jan-1998; Class I: Logic; Class II: Buffer/Line Driver
U6 = SN74ABT16244ADL: 16-Bit Buffer/Driver with 3-State Outputs; Manufacturer: Texas Instruments; Package Information: Latest Revision: Jan-1998; Class I: Logic; Class II: Buffer/Line Driver

## Sheet Buffer.SchDoc
size A4
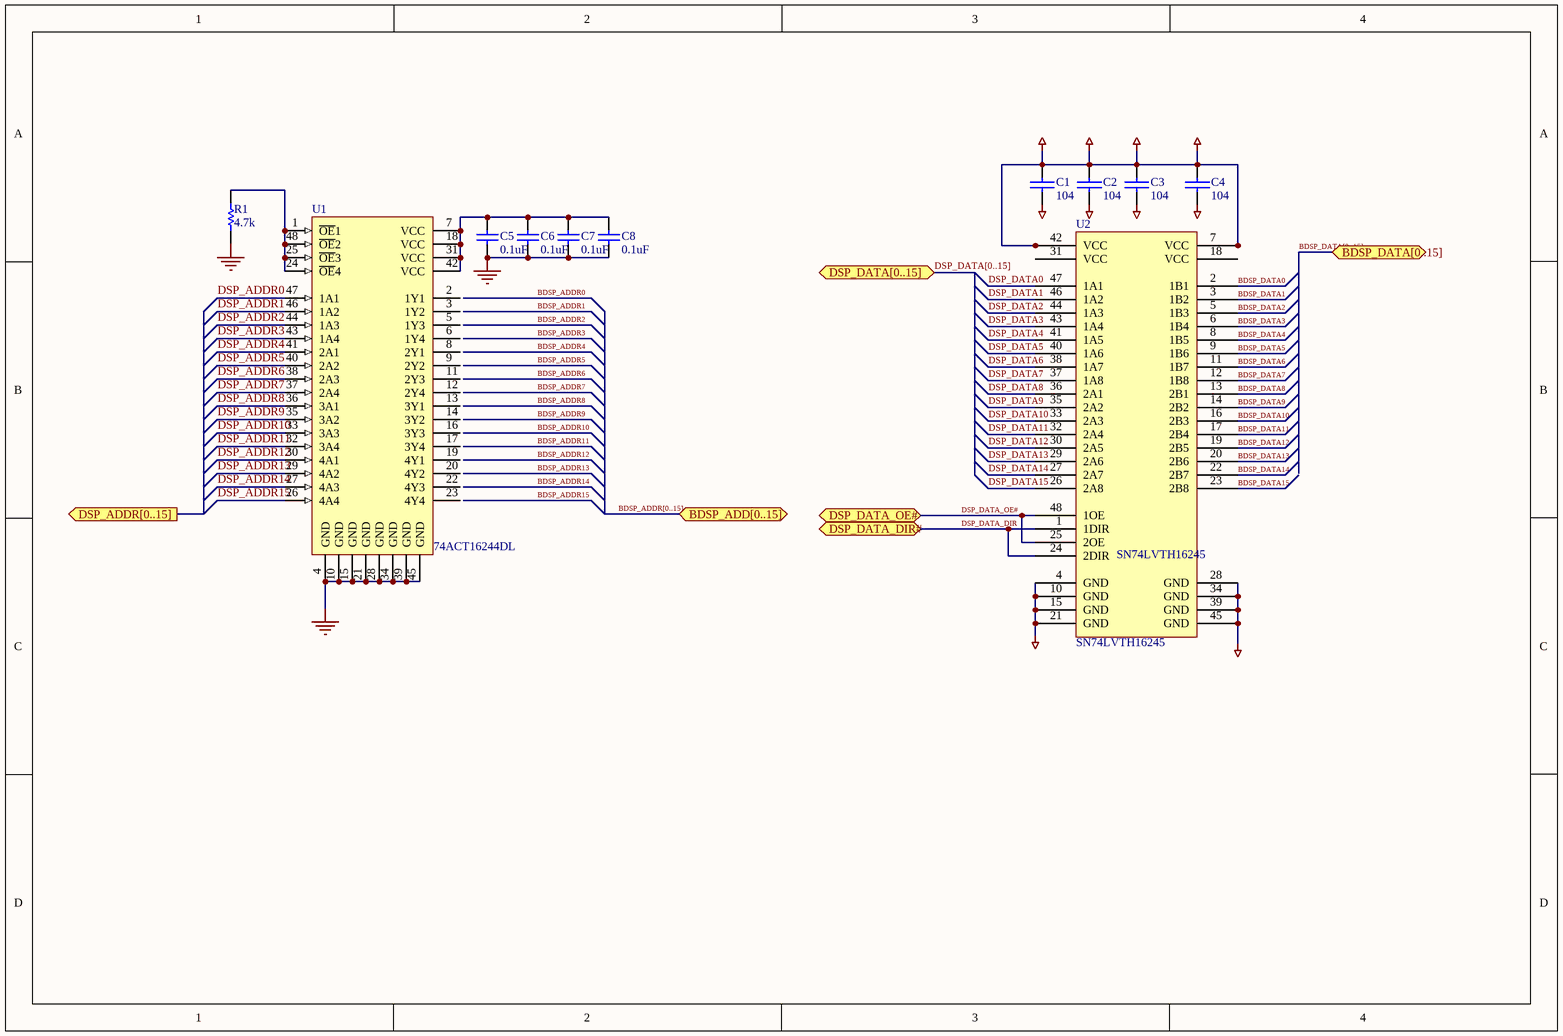
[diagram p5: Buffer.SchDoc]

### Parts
(Parts that share a designator on the sheet are numbered #1, #2 ... from top to bottom, then left to right.)
C1#1  104  [0805]
C2#1  104  [0805]
C3#1  104  [0805]
C4#1  104  [0805]
C5#1  0.1uF  [RAD-0.3]
C6#1  0.1uF  [RAD-0.3]
C7#1  0.1uF  [RAD-0.3]
C8#1  0.1uF  [RAD-0.3]
R1  4.7k  [AXIAL-0.3]
U1#1  74ACT16244DL  [SSO-G48]
U2  SN74LVTH16245  [TSOP48]

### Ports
BDSP_ADD[0..15], BDSP_DATA[0..15], DSP_ADDR[0..15] (out), DSP_DATA[0..15], DSP_DATA_DIR#, DSP_DATA_OE#

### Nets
3.3V: C1#1.1 C2#1.1 C3#1.1 C4#1.1 U2.7(VCC) U2.42(VCC)
DGND: C1#1.2 C2#1.2 C3#1.2 C4#1.2 U2.4(GND) U2.10(GND) U2.15(GND) U2.21(GND) U2.28(GND) U2.34(GND) U2.39(GND) U2.45(GND)
GND: C5#1.1 C6#1.1 C7#1.1 C8#1.1 R1.1 U1#1.4(GND) U1#1.10(GND) U1#1.15(GND) U1#1.21(GND) U1#1.28(GND) U1#1.34(GND) U1#1.39(GND) U1#1.45(GND)
BDSP_DATA0: U2.2(1B1)
BDSP_DATA1: U2.3(1B2)
BDSP_DATA2: U2.5(1B3)
BDSP_DATA3: U2.6(1B4)
BDSP_DATA4: U2.8(1B5)
BDSP_DATA5: U2.9(1B6)
BDSP_DATA6: U2.11(1B7)
BDSP_DATA7: U2.12(1B8)
BDSP_DATA8: U2.13(2B1)
BDSP_DATA9: U2.14(2B2)
BDSP_DATA10: U2.16(2B3)
BDSP_DATA11: U2.17(2B4)
BDSP_DATA12: U2.19(2B5)
BDSP_DATA13: U2.20(2B6)
BDSP_DATA14: U2.22(2B7)
BDSP_DATA15: U2.23(2B8)
DSP_ADDR0: U1#1.47(1A1)
DSP_ADDR1: U1#1.46(1A2)
DSP_ADDR2: U1#1.44(1A3)
DSP_ADDR3: U1#1.43(1A4)
DSP_ADDR4: U1#1.41(2A1)
DSP_ADDR5: U1#1.40(2A2)
DSP_ADDR6: U1#1.38(2A3)
DSP_ADDR7: U1#1.37(2A4)
DSP_ADDR8: U1#1.36(3A1)
DSP_ADDR9: U1#1.35(3A2)
DSP_ADDR10: U1#1.33(3A3)
DSP_ADDR11: U1#1.32(3A4)
DSP_ADDR12: U1#1.30(4A1)
DSP_ADDR13: U1#1.29(4A2)
DSP_ADDR14: U1#1.27(4A3)
DSP_ADDR15: U1#1.26(4A4)
DSP_DATA0: U2.47(1A1)
DSP_DATA1: U2.46(1A2)
DSP_DATA2: U2.44(1A3)
DSP_DATA3: U2.43(1A4)
DSP_DATA4: U2.41(1A5)
DSP_DATA5: U2.40(1A6)
DSP_DATA6: U2.38(1A7)
DSP_DATA7: U2.37(1A8)
DSP_DATA8: U2.36(2A1)
DSP_DATA9: U2.35(2A2)
DSP_DATA10: U2.33(2A3)
DSP_DATA11: U2.32(2A4)
DSP_DATA12: U2.30(2A5)
DSP_DATA13: U2.29(2A6)
DSP_DATA14: U2.27(2A7)
DSP_DATA15: U2.26(2A8)
DSP_DATA_DIR: U2.1(1DIR) U2.24(2DIR) ; port DSP_DATA_DIR#
DSP_DATA_OE#: U2.25(2OE) U2.48(1OE) ; port DSP_DATA_OE#
NetC5#1_2: C5#1.2 C6#1.2 C7#1.2 C8#1.2 U1#1.7(VCC) U1#1.18(VCC) U1#1.31(VCC) U1#1.42(VCC)
NetR1_2: R1.2 U1#1.1(~{OE}1) U1#1.24(~{OE}4) U1#1.25(~{OE}3) U1#1.48(~{OE}2)

Not connected (* = marked no-connect by the designer): U1#1 2(1Y1) 3(1Y2) 5(1Y3) 6(1Y4) 8(2Y1) 9(2Y2) 11(2Y3) 12(2Y4) 13(3Y1) 14(3Y2) 16(3Y3) 17(3Y4) 19(4Y1) 20(4Y2) 22(4Y3) 23(4Y4); U2 18(VCC) 31(VCC)

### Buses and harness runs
bus BDSP_ADDR[0..15] = port BDSP_ADD[0..15]
bus BDSP_DATA[0..15] = port BDSP_DATA[0..15]
bus DSP_DATA[0..15] = port DSP_DATA[0..15]

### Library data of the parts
C1#1 C2#1 C3#1 C4#1 = CAP: Capacitor
C5#1 C6#1 C7#1 C8#1 = Cap: Capacitor; Manufacturer: Generic Components; Class I: Passive; Value: 100pF
R1 = Res1: Resistor; Manufacturer: Generic Components; Class I: Passive; Value: 1K
U1#1 = 74ACT16244DL: 16-Bit Buffer/Line Driver with 3-State Outputs; Manufacturer: Texas Instruments; Package Information: Latest Revision: Jan-1998; Class I: Logic

## Sheet Power.SchDoc
size A4
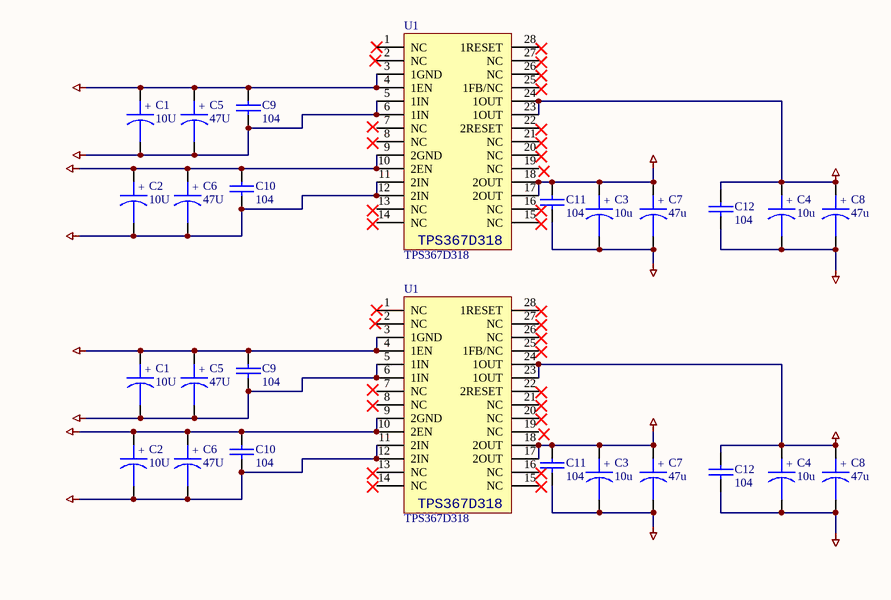
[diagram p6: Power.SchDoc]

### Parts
(Parts that share a designator on the sheet are numbered #1, #2 ... from top to bottom, then left to right.)
C1#2  10U  [RB5-10.5]
C1#3  10U  [RB5-10.5]
C2#2  10U  [RB5-10.5]
C2#3  10U  [RB5-10.5]
C3#2  10u  [RB5-10.5]
C3#3  10u  [RB5-10.5]
C4#2  10u  [RB5-10.5]
C4#3  10u  [RB5-10.5]
C5#2  47U  [RB5-10.5]
C5#3  47U  [RB5-10.5]
C6#2  47U  [RB5-10.5]
C6#3  47U  [RB5-10.5]
C7#2  47u  [RB5-10.5]
C7#3  47u  [RB5-10.5]
C8#2  47u  [RB5-10.5]
C8#3  47u  [RB5-10.5]
C9#2  104  [CC2012-0805]
C9#3  104  [CC2012-0805]
C10#2  104  [CC2012-0805]
C10#3  104  [CC2012-0805]
C11#2  104  [CC2012-0805]
C11#3  104  [CC2012-0805]
C12#2  104  [CC2012-0805]
C12#3  104  [CC2012-0805]
U1#2  TPS367D318  [TSSO10X6-G28]
U1#3  TPS367D318  [TSSO10X6-G28]

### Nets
1.8V: C4#2.1 C4#3.1 C8#2.1 C8#3.1 C12#2.1 C12#3.1 U1#2.23(1OUT) U1#2.24(1OUT) U1#3.23(1OUT) U1#3.24(1OUT)
3.3V: C3#2.1 C3#3.1 C7#2.1 C7#3.1 C11#2.1 C11#3.1 U1#2.17(2OUT) U1#2.18(2OUT) U1#3.17(2OUT) U1#3.18(2OUT)
5V: C1#2.2 C1#3.2 C2#2.2 C2#3.2 C5#2.2 C5#3.2 C6#2.2 C6#3.2 C9#2.2 C9#3.2 C10#2.2 C10#3.2 U1#2.5(1IN) U1#2.6(1IN) U1#2.11(2IN) U1#2.12(2IN) U1#3.5(1IN) U1#3.6(1IN) U1#3.11(2IN) U1#3.12(2IN)
DGND: C1#2.1 C1#3.1 C2#2.1 C2#3.1 C3#2.2 C3#3.2 C4#2.2 C4#3.2 C5#2.1 C5#3.1 C6#2.1 C6#3.1 C7#2.2 C7#3.2 C8#2.2 C8#3.2 C9#2.1 C9#3.1 C10#2.1 C10#3.1 C11#2.2 C11#3.2 C12#2.2 C12#3.2 U1#2.3(1GND) U1#2.4(1EN) U1#2.9(2GND) U1#2.10(2EN) U1#3.3(1GND) U1#3.4(1EN) U1#3.9(2GND) U1#3.10(2EN)

Not connected (* = marked no-connect by the designer): U1#2 1(NC)* 2(NC) 7(NC) 8(NC) 13(NC) 14(NC) 15(NC) 16(NC) 19(NC) 20(NC) 21(NC) 22(2RESET) 25(1FB/NC) 26(NC) 27(NC) 28(1RESET); U1#3 1(NC)* 2(NC) 7(NC) 8(NC) 13(NC) 14(NC) 15(NC) 16(NC) 19(NC) 20(NC) 21(NC) 22(2RESET) 25(1FB/NC) 26(NC) 27(NC) 28(1RESET)

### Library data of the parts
C1#2 C1#3 C2#2 C2#3 C3#2 C3#3 C4#2 C4#3 C5#2 C5#3 C6#2 C6#3 C7#2 C7#3 C8#2 C8#3 = CAPACITOR POL: Capacitor
C9#2 C9#3 C10#2 C10#3 C11#2 C11#3 C12#2 C12#3 = CAP: Capacitor
U1#2 U1#3 = TPS367D318: POWRE; Manufacturer: Texas Instruments

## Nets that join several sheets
1.8V: DSP_Main (14 pins), Power (10 pins)
3.3V: DSP_Main (25 pins), CPLD (13 pins), Memory (5 pins), Interface (8 pins), Interface2 (22 pins), Buffer (6 pins), Power (10 pins)
5V: CPLD (C15.2 C16.2 U3.3 U3.43), Memory (U9.20 U10.20 U11.20), Power (20 pins)
DGND: DSP_Main (43 pins), CPLD (18 pins), Memory (14 pins), Interface (25 pins), Interface2 (28 pins), Buffer (12 pins), Power (32 pins)
BDSP_DATA0: CPLD (U3.45), Memory (U9.2 U12.29 U13.7), Buffer (U2.2)
BDSP_DATA1: CPLD (U3.46), Memory (U9.3 U12.31 U13.8), Buffer (U2.3)
BDSP_DATA2: CPLD (U3.44), Memory (U9.4 U12.33 U13.9), Buffer (U2.5)
BDSP_DATA3: CPLD (U3.41), Memory (U9.5 U12.35 U13.10), Buffer (U2.6)
BDSP_DATA4: CPLD (U3.39), Memory (U9.6 U12.38 U13.13), Buffer (U2.8)
BDSP_DATA5: CPLD (U3.37), Memory (U9.7 U12.40 U13.14), Buffer (U2.9)
BDSP_DATA6: CPLD (U3.35), Memory (U9.8 U12.42 U13.15), Buffer (U2.11)
BDSP_DATA7: CPLD (U3.33), Memory (U9.9 U12.44 U13.16), Buffer (U2.12)
BDSP_DATA8: CPLD (U3.36), Memory (U12.30 U13.29), Buffer (U2.13)
BDSP_DATA9: CPLD (U3.34), Memory (U12.32 U13.30), Buffer (U2.14)
BDSP_DATA10: CPLD (U3.30), Memory (U12.34 U13.31), Buffer (U2.16)
BDSP_DATA11: CPLD (U3.31), Memory (U12.36 U13.32), Buffer (U2.17)
BDSP_DATA12: CPLD (U3.28), Memory (U12.39 U13.35), Buffer (U2.19)
BDSP_DATA13: CPLD (U3.29), Memory (U12.41 U13.36), Buffer (U2.20)
BDSP_DATA14: CPLD (U3.27), Memory (U12.43 U13.37), Buffer (U2.22)
BDSP_DATA15: CPLD (U3.24), Memory (U12.45 U13.38), Buffer (U2.23)
DSP_CLKOUT: DSP_Main (U£¿2.94), CPLD (U3.83)
DSP_DATA0: DSP_Main (U£¿2.99), Buffer (U2.47)
DSP_DATA1: DSP_Main (U£¿2.100), Buffer (U2.46)
DSP_DATA2: DSP_Main (U£¿2.101), Buffer (U2.44)
DSP_DATA3: DSP_Main (U£¿2.102), Buffer (U2.43)
DSP_DATA4: DSP_Main (U£¿2.103), Buffer (U2.41)
DSP_DATA5: DSP_Main (U£¿2.104), Buffer (U2.40)
DSP_DATA6: DSP_Main (U£¿2.113), Buffer (U2.38)
DSP_DATA7: DSP_Main (U£¿2.114), Buffer (U2.37)
DSP_DATA8: DSP_Main (U£¿2.115), Buffer (U2.36)
DSP_DATA9: DSP_Main (U£¿2.116), Buffer (U2.35)
DSP_DATA10: DSP_Main (U£¿2.117), Buffer (U2.33)
DSP_DATA11: DSP_Main (U£¿2.118), Buffer (U2.32)
DSP_DATA12: DSP_Main (U£¿2.119), Buffer (U2.30)
DSP_DATA13: DSP_Main (U£¿2.121), Buffer (U2.29)
DSP_DATA14: DSP_Main (U£¿2.122), Buffer (U2.27)
DSP_DATA15: DSP_Main (U£¿2.123), Buffer (U2.26)
DSP_DATA_DIR: CPLD (U3.77), Buffer (U2.1 U2.24)
DSP_DATA_OE#: CPLD (U3.75), Buffer (U2.25 U2.48)
DSP_DS#: DSP_Main (U£¿2.21), CPLD (U3.73)
DSP_HOLD#: DSP_Main (R11.2 U£¿2.30), CPLD (U3.65)
DSP_INT0#: DSP_Main (R4.2 U£¿2.64), Interface2 (U6.2)
DSP_INT1#: DSP_Main (R5.2 U£¿2.65), Interface2 (U6.3)
DSP_INT2#: DSP_Main (R6.2 U£¿2.66), Interface2 (U6.5)
DSP_INT3#: DSP_Main (R7.2 U£¿2.67), Interface2 (U6.6)
DSP_IOSTRS#: DSP_Main (U£¿2.25), CPLD (U3.67)
DSP_IS#: DSP_Main (U£¿2.22), CPLD (U3.70)
DSP_MPMC: DSP_Main (R10.2 U£¿2.32), Interface2 (R18.1 S2.5)
DSP_MSTRS#: DSP_Main (U£¿2.24), CPLD (U3.68)
DSP_NMI#: DSP_Main (R8.2 U£¿2.63), CPLD (U3.58)
DSP_PS#: DSP_Main (U£¿2.20), CPLD (U3.74)
DSP_R/W#: DSP_Main (U£¿2.23), CPLD (U3.69)
DSP_RST#: DSP_Main (R9.2 U£¿2.98), CPLD (U3.81)
FLASH_BYTE: CPLD (U3.57), Memory (U12.47)
FLASH_CE#: CPLD (U3.55), Memory (U12.26)
FLASH_RB: CPLD (U3.51), Memory (U12.15)
FLASH_RP: CPLD (U3.52), Memory (U12.12)
H_HBIL: DSP_Main (U£¿2.62), Interface2 (JP3.4)
H_HCNTL0: DSP_Main (U£¿2.39), Interface2 (JP3.16)
H_HCNTL1: DSP_Main (U£¿2.46), Interface2 (JP3.12)
H_R/W#: DSP_Main (U£¿2.18), Interface2 (JP3.15)
HAS#: DSP_Main (U£¿2.13), Interface2 (JP3.13)
HCS0: DSP_Main (U£¿2.17), Interface2 (JP3.14)
MEM_R#: CPLD (U3.49), Memory (U12.28 U13.41), Interface2 (U5.47)
MEM_WE#: CPLD (U3.50), Memory (U12.11 U13.17), Interface2 (U5.46)
NetJP3_8: DSP_Main (U£¿2.127), Interface2 (JP3.8)
NetJP3_9: DSP_Main (U£¿2.129), Interface2 (JP3.9)
NetR14_1: CPLD (U3.60), Interface2 (R14.1 S1.1)
NetR15_1: DSP_Main (U£¿2.79), Interface2 (R15.1 S2.8)
NetR16_1: DSP_Main (U£¿2.78), Interface2 (R16.1 S2.7)
NetR17_1: DSP_Main (U£¿2.77), Interface2 (R17.1 S2.6)
NetU3_54: CPLD (U3.54), Memory (U9.11)
NetU3_63: CPLD (U3.63), Interface (U7.1 U7.24), Interface2 (U5.44)
NetU3_76: DSP_Main (U£¿2.19), CPLD (U3.76)
NetU3_79: CPLD (U3.79), Memory (U10.11 U11.11)
NetU3_80: CPLD (U3.80), Interface (U7.25 U7.48)
NetU5_16: DSP_Main (U£¿2.47), Interface2 (U5.16)
NetU5_17: DSP_Main (U£¿2.45), Interface2 (U5.17)
NetU5_19: DSP_Main (U£¿2.44), Interface2 (U5.19)
NetU5_20: DSP_Main (U£¿2.43), Interface2 (U5.20)
NetU5_22: DSP_Main (U£¿2.42), Interface2 (U5.22)
NetU5_23: DSP_Main (U£¿2.41), Interface2 (U5.23)
NetU5_35: DSP_Main (U£¿2.48), Interface2 (U5.35)
NetU5_36: DSP_Main (U£¿2.49), Interface2 (U5.36)
NetU5_37: DSP_Main (U£¿2.51), Interface2 (U5.37)
NetU5_38: DSP_Main (U£¿2.53), Interface2 (U5.38)
NetU5_40: DSP_Main (U£¿2.54), Interface2 (U5.40)
NetU5_41: DSP_Main (U£¿2.55), Interface2 (U5.41)
NetU5_43: DSP_Main (U£¿2.59), Interface2 (U5.43)
SRAM_CE#: CPLD (U3.48), Memory (U13.6)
